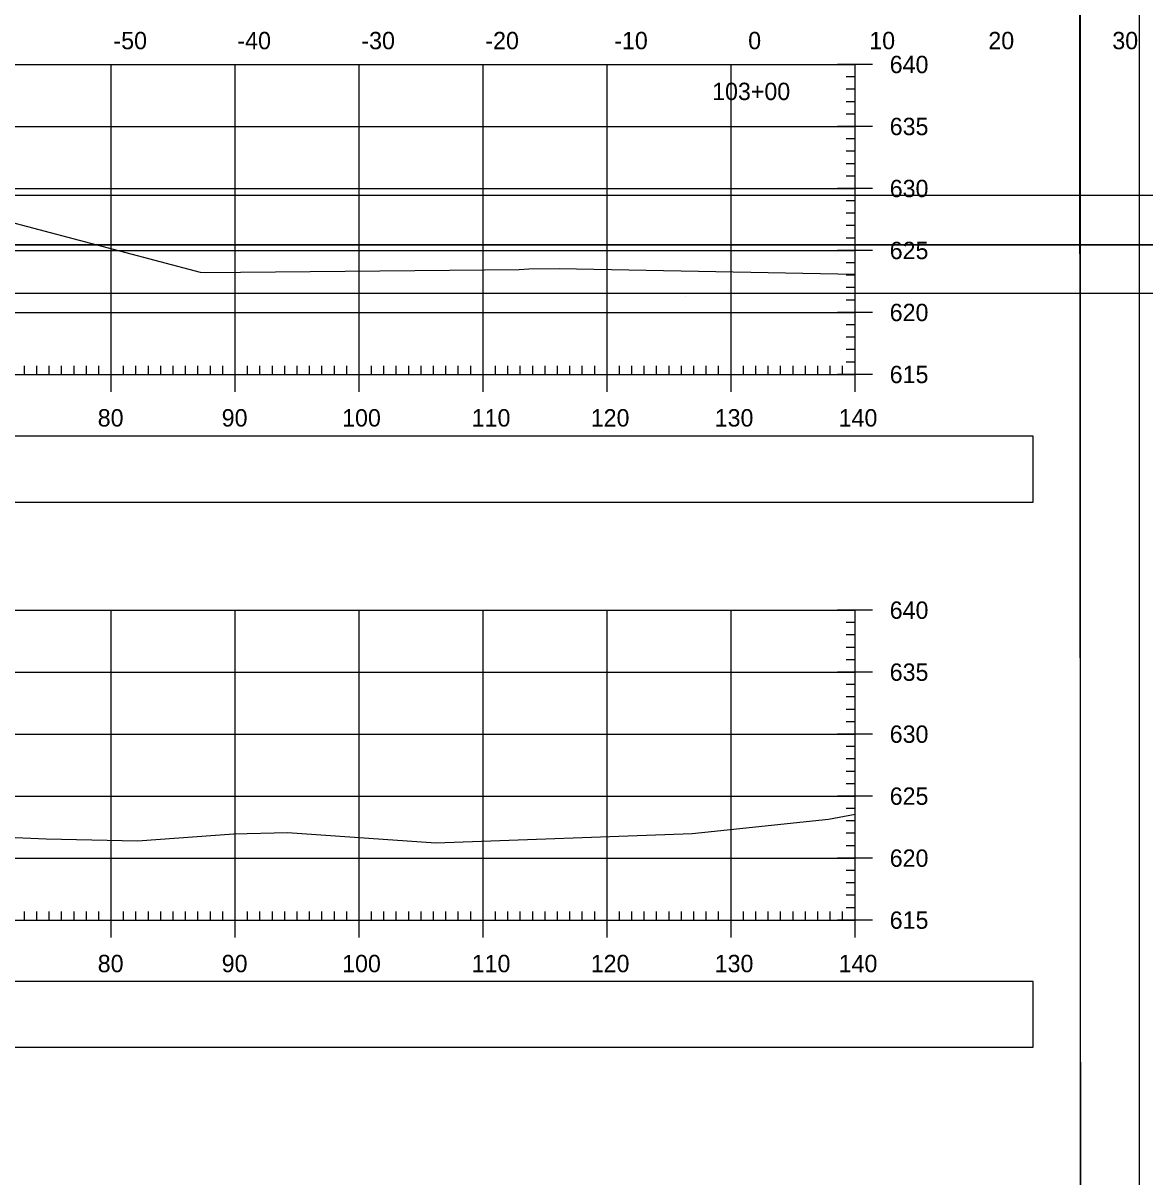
# Model space of a CAD drawing. Extents: x 1381471 to 1382703, y 370300 to 371487.
# Drawn here: x 1382077.7 to 1382168.2, y 370772 to 370865 of the extents above; entities that cross this region are included whole.
import ezdxf

# ---------------------------------------------------------------- set-up
doc = ezdxf.new("R2010")
doc.units = 0
for name, color, linetype in [('Level 18', 7, 'Continuous'), ('Level 22', 7, 'Continuous'), ('Level 26', 7, 'Continuous'), ('Level 4', 7, 'Continuous'), ('Level 45', 7, 'Continuous'), ('Level 5', 7, 'Continuous'), ('Level 6', 7, 'Continuous')]:
    doc.layers.add(name, color=color, linetype=linetype)

msp = doc.modelspace()

# ---------------------------------------------------------------- linework, layer by layer
at = {"layer": 'Level 18'}
for points in [[(1381986.639, 370854.131), (1381995.441, 370854.317), (1382001.903, 370854.37), (1382006.177, 370854.378), (1382010.508, 370854.233), (1382016.454, 370854.043), (1382017.738, 370853.933), (1382019.06, 370853.849), (1382020.004, 370853.756), (1382024.738, 370853.599), (1382030.583, 370853.56), (1382040.341, 370853.292), (1382045.103, 370853.174), (1382052.493, 370852.938), (1382062.195, 370852.629), (1382072.39, 370850.094), (1382091.946, 370844.952), (1382092.414, 370844.91), (1382117.68, 370845.162), (1382118.449, 370845.197), (1382120.92, 370845.224), (1382144.772, 370844.774)], [(1381947.353, 370799.265), (1381988.698, 370799.103), (1381992.353, 370799.97), (1381993.354, 370800.244), (1382013.021, 370798.303), (1382014.226, 370798.141), (1382014.707, 370798.032), (1382018.159, 370797.726), (1382022.298, 370798.605), (1382029.855, 370799.193), (1382038.801, 370799.717), (1382052.694, 370799.603), (1382053.325, 370799.965), (1382058.303, 370800.151), (1382079.532, 370799.229), (1382086.886, 370799.083), (1382094.654, 370799.642), (1382099.004, 370799.754), (1382110.953, 370798.923), (1382131.63, 370799.658), (1382142.637, 370800.83), (1382144.772, 370801.226)]]:
    msp.add_lwpolyline(points, dxfattribs=at)
at = {"layer": 'Level 22'}
for p, q in [((1381864.772, 370861.691), (1382144.772, 370861.691)), ((1382084.772, 370836.691), (1382084.772, 370861.691)), ((1382094.772, 370836.691), (1382094.772, 370861.691)), ((1382104.772, 370836.691), (1382104.772, 370861.691)), ((1382114.772, 370836.691), (1382114.772, 370861.691)), ((1382124.772, 370836.691), (1382124.772, 370861.691)), ((1382134.772, 370836.691), (1382134.772, 370861.691)), ((1382144.772, 370836.691), (1382144.772, 370861.691)), ((1381864.772, 370856.691), (1382144.772, 370856.691)), ((1381864.772, 370851.691), (1382144.772, 370851.691)), ((1381864.772, 370846.691), (1382144.772, 370846.691)), ((1381864.772, 370841.691), (1382144.772, 370841.691)), ((1381864.772, 370836.691), (1382144.772, 370836.691)), ((1381864.772, 370817.68), (1382144.772, 370817.68)), ((1382084.772, 370792.68), (1382084.772, 370817.68)), ((1382094.772, 370792.68), (1382094.772, 370817.68)), ((1382104.772, 370792.68), (1382104.772, 370817.68)), ((1382114.772, 370792.68), (1382114.772, 370817.68)), ((1382124.772, 370792.68), (1382124.772, 370817.68)), ((1382134.772, 370792.68), (1382134.772, 370817.68)), ((1382144.772, 370792.68), (1382144.772, 370817.68)), ((1381864.772, 370812.68), (1382144.772, 370812.68)), ((1381864.772, 370807.68), (1382144.772, 370807.68)), ((1381864.772, 370802.68), (1382144.772, 370802.68)), ((1381864.772, 370797.68), (1382144.772, 370797.68)), ((1381864.772, 370792.68), (1382144.772, 370792.68))]:
    msp.add_line(p, q, dxfattribs=at)
at = {"layer": 'Level 26'}
for points in [[(1381834.365, 370974.304), (1382167.705, 370974.304), (1382167.705, 370760.966), (1381834.365, 370760.966)], [(1382080.692, 370970.409), (1382100.312, 370970.409), (1382100.312, 370960.529), (1382116.424, 370960.529), (1382139.624, 370960.529), (1382139.624, 370927.859), (1382162.831, 370927.859), (1382162.952, 370764.949), (1381846.772, 370764.949), (1381846.772, 370970.409)]]:
    msp.add_lwpolyline(points, close=True, dxfattribs=at)
at = {"layer": 'Level 4'}
for p, q in [((1382146.172, 370861.691), (1382143.372, 370861.691)), ((1382144.772, 370836.691), (1382144.772, 370861.691)), ((1382144.772, 370860.691), (1382144.072, 370860.691)), ((1382144.772, 370859.691), (1382144.072, 370859.691)), ((1382144.772, 370858.691), (1382144.072, 370858.691)), ((1382144.772, 370857.691), (1382144.072, 370857.691)), ((1382146.172, 370856.691), (1382143.372, 370856.691)), ((1382144.772, 370855.691), (1382144.072, 370855.691)), ((1382144.772, 370854.691), (1382144.072, 370854.691)), ((1382144.772, 370853.691), (1382144.072, 370853.691)), ((1382144.772, 370852.691), (1382144.072, 370852.691)), ((1382146.172, 370851.691), (1382143.372, 370851.691)), ((1382144.772, 370850.691), (1382144.072, 370850.691)), ((1382144.772, 370849.691), (1382144.072, 370849.691)), ((1382144.772, 370848.691), (1382144.072, 370848.691)), ((1382144.772, 370847.691), (1382144.072, 370847.691)), ((1382146.172, 370846.691), (1382143.372, 370846.691)), ((1382144.772, 370845.691), (1382144.072, 370845.691)), ((1382144.772, 370844.691), (1382144.072, 370844.691)), ((1382144.772, 370843.691), (1382144.072, 370843.691)), ((1382144.772, 370842.691), (1382144.072, 370842.691)), ((1382146.172, 370841.691), (1382143.372, 370841.691)), ((1382144.772, 370840.691), (1382144.072, 370840.691)), ((1382144.772, 370839.691), (1382144.072, 370839.691)), ((1382084.772, 370835.291), (1382084.772, 370838.091)), ((1382094.772, 370835.291), (1382094.772, 370838.091)), ((1382104.772, 370835.291), (1382104.772, 370838.091)), ((1382114.772, 370835.291), (1382114.772, 370838.091)), ((1382124.772, 370835.291), (1382124.772, 370838.091)), ((1382134.772, 370835.291), (1382134.772, 370838.091)), ((1382144.772, 370838.691), (1382144.072, 370838.691)), ((1382144.772, 370835.291), (1382144.772, 370838.091)), ((1382077.772, 370836.691), (1382077.772, 370837.391)), ((1382078.772, 370836.691), (1382078.772, 370837.391)), ((1382079.772, 370836.691), (1382079.772, 370837.391)), ((1382080.772, 370836.691), (1382080.772, 370837.391)), ((1382081.772, 370836.691), (1382081.772, 370837.391)), ((1382082.772, 370836.691), (1382082.772, 370837.391)), ((1382083.772, 370836.691), (1382083.772, 370837.391)), ((1382085.772, 370836.691), (1382085.772, 370837.391)), ((1382086.772, 370836.691), (1382086.772, 370837.391)), ((1382087.772, 370836.691), (1382087.772, 370837.391)), ((1382088.772, 370836.691), (1382088.772, 370837.391)), ((1382089.772, 370836.691), (1382089.772, 370837.391)), ((1382090.772, 370836.691), (1382090.772, 370837.391)), ((1382091.772, 370836.691), (1382091.772, 370837.391)), ((1382092.772, 370836.691), (1382092.772, 370837.391)), ((1382093.772, 370836.691), (1382093.772, 370837.391)), ((1382095.772, 370836.691), (1382095.772, 370837.391)), ((1382096.772, 370836.691), (1382096.772, 370837.391)), ((1382097.772, 370836.691), (1382097.772, 370837.391)), ((1382098.772, 370836.691), (1382098.772, 370837.391)), ((1382099.772, 370836.691), (1382099.772, 370837.391)), ((1382100.772, 370836.691), (1382100.772, 370837.391)), ((1382101.772, 370836.691), (1382101.772, 370837.391)), ((1382102.772, 370836.691), (1382102.772, 370837.391)), ((1382103.772, 370836.691), (1382103.772, 370837.391)), ((1382105.772, 370836.691), (1382105.772, 370837.391)), ((1382106.772, 370836.691), (1382106.772, 370837.391)), ((1382107.772, 370836.691), (1382107.772, 370837.391)), ((1382108.772, 370836.691), (1382108.772, 370837.391)), ((1382109.772, 370836.691), (1382109.772, 370837.391)), ((1382110.772, 370836.691), (1382110.772, 370837.391)), ((1382111.772, 370836.691), (1382111.772, 370837.391)), ((1382112.772, 370836.691), (1382112.772, 370837.391)), ((1382113.772, 370836.691), (1382113.772, 370837.391)), ((1382115.772, 370836.691), (1382115.772, 370837.391)), ((1382116.772, 370836.691), (1382116.772, 370837.391)), ((1382117.772, 370836.691), (1382117.772, 370837.391)), ((1382118.772, 370836.691), (1382118.772, 370837.391)), ((1382119.772, 370836.691), (1382119.772, 370837.391)), ((1382120.772, 370836.691), (1382120.772, 370837.391)), ((1382121.772, 370836.691), (1382121.772, 370837.391)), ((1382122.772, 370836.691), (1382122.772, 370837.391)), ((1382123.772, 370836.691), (1382123.772, 370837.391)), ((1382125.772, 370836.691), (1382125.772, 370837.391)), ((1382126.772, 370836.691), (1382126.772, 370837.391)), ((1382127.772, 370836.691), (1382127.772, 370837.391)), ((1382128.772, 370836.691), (1382128.772, 370837.391)), ((1382129.772, 370836.691), (1382129.772, 370837.391)), ((1382130.772, 370836.691), (1382130.772, 370837.391)), ((1382131.772, 370836.691), (1382131.772, 370837.391)), ((1382132.772, 370836.691), (1382132.772, 370837.391)), ((1382133.772, 370836.691), (1382133.772, 370837.391)), ((1382135.772, 370836.691), (1382135.772, 370837.391)), ((1382136.772, 370836.691), (1382136.772, 370837.391)), ((1382137.772, 370836.691), (1382137.772, 370837.391)), ((1382138.772, 370836.691), (1382138.772, 370837.391)), ((1382139.772, 370836.691), (1382139.772, 370837.391)), ((1382140.772, 370836.691), (1382140.772, 370837.391)), ((1382141.772, 370836.691), (1382141.772, 370837.391)), ((1382142.772, 370836.691), (1382142.772, 370837.391)), ((1382143.772, 370836.691), (1382143.772, 370837.391)), ((1382144.772, 370837.691), (1382144.072, 370837.691)), ((1381864.772, 370836.691), (1382144.772, 370836.691)), ((1382146.172, 370836.691), (1382143.372, 370836.691)), ((1382146.172, 370817.68), (1382143.372, 370817.68)), ((1382144.772, 370792.68), (1382144.772, 370817.68)), ((1382144.772, 370816.68), (1382144.072, 370816.68)), ((1382144.772, 370815.68), (1382144.072, 370815.68)), ((1382144.772, 370814.68), (1382144.072, 370814.68)), ((1382144.772, 370813.68), (1382144.072, 370813.68)), ((1382146.172, 370812.68), (1382143.372, 370812.68)), ((1382144.772, 370811.68), (1382144.072, 370811.68)), ((1382144.772, 370810.68), (1382144.072, 370810.68)), ((1382144.772, 370809.68), (1382144.072, 370809.68)), ((1382144.772, 370808.68), (1382144.072, 370808.68)), ((1382146.172, 370807.68), (1382143.372, 370807.68)), ((1382144.772, 370806.68), (1382144.072, 370806.68)), ((1382144.772, 370805.68), (1382144.072, 370805.68)), ((1382144.772, 370804.68), (1382144.072, 370804.68)), ((1382144.772, 370803.68), (1382144.072, 370803.68)), ((1382146.172, 370802.68), (1382143.372, 370802.68)), ((1382144.772, 370801.68), (1382144.072, 370801.68)), ((1382144.772, 370800.68), (1382144.072, 370800.68)), ((1382144.772, 370799.68), (1382144.072, 370799.68)), ((1382144.772, 370798.68), (1382144.072, 370798.68)), ((1382146.172, 370797.68), (1382143.372, 370797.68)), ((1382144.772, 370796.68), (1382144.072, 370796.68)), ((1382144.772, 370795.68), (1382144.072, 370795.68)), ((1382144.772, 370794.68), (1382144.072, 370794.68)), ((1382077.772, 370792.68), (1382077.772, 370793.38)), ((1382078.772, 370792.68), (1382078.772, 370793.38)), ((1382079.772, 370792.68), (1382079.772, 370793.38)), ((1382080.772, 370792.68), (1382080.772, 370793.38)), ((1382081.772, 370792.68), (1382081.772, 370793.38)), ((1382082.772, 370792.68), (1382082.772, 370793.38)), ((1382083.772, 370792.68), (1382083.772, 370793.38)), ((1382084.772, 370791.28), (1382084.772, 370794.08)), ((1382085.772, 370792.68), (1382085.772, 370793.38)), ((1382086.772, 370792.68), (1382086.772, 370793.38)), ((1382087.772, 370792.68), (1382087.772, 370793.38)), ((1382088.772, 370792.68), (1382088.772, 370793.38)), ((1382089.772, 370792.68), (1382089.772, 370793.38)), ((1382090.772, 370792.68), (1382090.772, 370793.38)), ((1382091.772, 370792.68), (1382091.772, 370793.38)), ((1382092.772, 370792.68), (1382092.772, 370793.38)), ((1382093.772, 370792.68), (1382093.772, 370793.38)), ((1382094.772, 370791.28), (1382094.772, 370794.08)), ((1382095.772, 370792.68), (1382095.772, 370793.38)), ((1382096.772, 370792.68), (1382096.772, 370793.38)), ((1382097.772, 370792.68), (1382097.772, 370793.38)), ((1382098.772, 370792.68), (1382098.772, 370793.38)), ((1382099.772, 370792.68), (1382099.772, 370793.38)), ((1382100.772, 370792.68), (1382100.772, 370793.38)), ((1382101.772, 370792.68), (1382101.772, 370793.38)), ((1382102.772, 370792.68), (1382102.772, 370793.38)), ((1382103.772, 370792.68), (1382103.772, 370793.38)), ((1382104.772, 370791.28), (1382104.772, 370794.08)), ((1382105.772, 370792.68), (1382105.772, 370793.38)), ((1382106.772, 370792.68), (1382106.772, 370793.38)), ((1382107.772, 370792.68), (1382107.772, 370793.38)), ((1382108.772, 370792.68), (1382108.772, 370793.38)), ((1382109.772, 370792.68), (1382109.772, 370793.38)), ((1382110.772, 370792.68), (1382110.772, 370793.38)), ((1382111.772, 370792.68), (1382111.772, 370793.38)), ((1382112.772, 370792.68), (1382112.772, 370793.38)), ((1382113.772, 370792.68), (1382113.772, 370793.38)), ((1382114.772, 370791.28), (1382114.772, 370794.08)), ((1382115.772, 370792.68), (1382115.772, 370793.38)), ((1382116.772, 370792.68), (1382116.772, 370793.38)), ((1382117.772, 370792.68), (1382117.772, 370793.38)), ((1382118.772, 370792.68), (1382118.772, 370793.38)), ((1382119.772, 370792.68), (1382119.772, 370793.38)), ((1382120.772, 370792.68), (1382120.772, 370793.38)), ((1382121.772, 370792.68), (1382121.772, 370793.38)), ((1382122.772, 370792.68), (1382122.772, 370793.38)), ((1382123.772, 370792.68), (1382123.772, 370793.38)), ((1382124.772, 370791.28), (1382124.772, 370794.08)), ((1382125.772, 370792.68), (1382125.772, 370793.38)), ((1382126.772, 370792.68), (1382126.772, 370793.38)), ((1382127.772, 370792.68), (1382127.772, 370793.38)), ((1382128.772, 370792.68), (1382128.772, 370793.38)), ((1382129.772, 370792.68), (1382129.772, 370793.38)), ((1382130.772, 370792.68), (1382130.772, 370793.38)), ((1382131.772, 370792.68), (1382131.772, 370793.38)), ((1382132.772, 370792.68), (1382132.772, 370793.38)), ((1382133.772, 370792.68), (1382133.772, 370793.38)), ((1382134.772, 370791.28), (1382134.772, 370794.08)), ((1382135.772, 370792.68), (1382135.772, 370793.38)), ((1382136.772, 370792.68), (1382136.772, 370793.38)), ((1382137.772, 370792.68), (1382137.772, 370793.38)), ((1382138.772, 370792.68), (1382138.772, 370793.38)), ((1382139.772, 370792.68), (1382139.772, 370793.38)), ((1382140.772, 370792.68), (1382140.772, 370793.38)), ((1382141.772, 370792.68), (1382141.772, 370793.38)), ((1382142.772, 370792.68), (1382142.772, 370793.38)), ((1382143.772, 370792.68), (1382143.772, 370793.38)), ((1382144.772, 370793.68), (1382144.072, 370793.68)), ((1382144.772, 370791.28), (1382144.772, 370794.08)), ((1381864.772, 370792.68), (1382144.772, 370792.68)), ((1382146.172, 370792.68), (1382143.372, 370792.68))]:
    msp.add_line(p, q, dxfattribs=at)
at = {"layer": 'Level 45'}
for p, q in [((1382294.793, 370851.12), (1381978.613, 370851.12)), ((1381966.213, 370847.142), (1382299.546, 370847.142)), ((1381966.213, 370847.137), (1382299.546, 370847.137)), ((1381978.613, 370843.242), (1382294.793, 370843.242)), ((1382131.133, 370842.982), (1382131.133, 370842.982)), ((1382131.133, 370842.982), (1382131.133, 370842.982))]:
    msp.add_line(p, q, dxfattribs=at)
for points in [[(1381966.206, 371060.475), (1382299.546, 371060.475), (1382299.546, 370847.137), (1381966.206, 370847.137)], [(1382212.533, 371056.58), (1382232.153, 371056.58), (1382232.153, 371046.7), (1382248.266, 371046.7), (1382271.465, 371046.7), (1382271.465, 371022.368), (1382294.793, 371022.368), (1382294.793, 370851.12), (1381978.613, 370851.12), (1381978.613, 371056.58)], [(1381966.206, 370847.137), (1382299.546, 370847.137), (1382299.546, 370633.799), (1381966.206, 370633.799)], [(1382212.533, 370843.242), (1382232.153, 370843.242), (1382232.153, 370833.362), (1382248.266, 370833.362), (1382271.465, 370833.362), (1382271.465, 370809.03), (1382294.793, 370809.03), (1382294.793, 370637.782), (1381978.613, 370637.782), (1381978.613, 370843.242)]]:
    msp.add_lwpolyline(points, close=True, dxfattribs=at)
at = {"layer": 'Level 6'}
msp.add_line((1382162.952, 370764.949), (1382162.952, 370970.409), dxfattribs=at)
for points in [[(1381850.409, 370826.389), (1382159.135, 370826.389), (1382159.135, 370831.711), (1381850.409, 370831.711)], [(1381850.409, 370782.42), (1382159.135, 370782.42), (1382159.135, 370787.741), (1381850.409, 370787.741)]]:
    msp.add_lwpolyline(points, close=True, dxfattribs=at)

# ---------------------------------------------------------------- texts
at = {"layer": 'Level 45'}
for s, p in [('-50', (1382084.954, 370862.92)), ('-40', (1382094.954, 370862.92)), ('-30', (1382104.954, 370862.92)), ('-20', (1382114.954, 370862.92)), ('-10', (1382125.351, 370862.92)), ('0', (1382136.156, 370862.92)), ('10', (1382145.924, 370862.92)), ('20', (1382155.528, 370862.92)), ('30', (1382165.528, 370862.92)), ('103+00', (1382133.246, 370858.82))]:
    msp.add_text(s, height=1.4, dxfattribs=at).set_placement(p)
at = {"layer": 'Level 5'}
for s, p in [('640', (1382147.572, 370860.991)), ('635', (1382147.572, 370855.991)), ('630', (1382147.572, 370850.991)), ('625', (1382147.572, 370845.991)), ('620', (1382147.572, 370840.991)), ('615', (1382147.572, 370835.991)), ('80', (1382083.686, 370832.491)), ('90', (1382093.686, 370832.491)), ('100', (1382103.4, 370832.491)), ('110', (1382113.852, 370832.491)), ('120', (1382123.455, 370832.491)), ('130', (1382133.455, 370832.491)), ('140', (1382143.455, 370832.491)), ('640', (1382147.572, 370816.98)), ('635', (1382147.572, 370811.98)), ('630', (1382147.572, 370806.98)), ('625', (1382147.572, 370801.98)), ('620', (1382147.572, 370796.98)), ('615', (1382147.572, 370791.98)), ('80', (1382083.686, 370788.48)), ('90', (1382093.686, 370788.48)), ('100', (1382103.4, 370788.48)), ('110', (1382113.852, 370788.48)), ('120', (1382123.455, 370788.48)), ('130', (1382133.455, 370788.48)), ('140', (1382143.455, 370788.48))]:
    msp.add_text(s, height=1.4, dxfattribs=at).set_placement(p)

doc.saveas('drawing.dxf')
